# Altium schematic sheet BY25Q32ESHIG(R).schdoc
size 127 x 101 mm
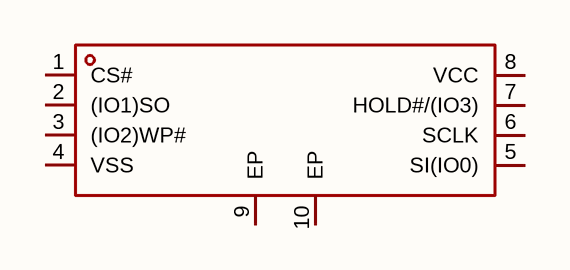
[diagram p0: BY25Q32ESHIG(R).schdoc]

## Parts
U?  by25q32eshig(r)  [DFN-8_L4.0-W3.0-P0.80-TL-EP_GT5YL24A1Y520]  (value not drawn)

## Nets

Not connected (* = marked no-connect by the designer): U? 1(CS#) 2((IO1)SO) 3((IO2)WP#) 4(VSS) 5(SI(IO0)) 6(SCLK) 7(HOLD#/(IO3)) 8(VCC) 9(EP) 10(EP)

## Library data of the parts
U? = by25q32eshig(r): 接口类型:SPI;存储容量:32Mbit;时钟频率(fc):120MHz;; Manufacturer: BOYAMICRO(博雅); AddInBom: yes; ModelId: ff23eaa3f9d946d4b17f951d9dd449de; ModelTransform: 118.18874,157.48,0,0,0,0,0,0,0; Interface: SPI; Memory Size: 32Mbit; Clock Frequency: 120MHz; Voltage - Supply: 2.7V~3.6V; Standby Supply Current: 2uA; Program / Erase Cycles: 100000次; Page Programming Time (Tpp): 450us; Block Erase Time(tBE): 180ms@(64KB); Data Retention - TDR (Year): 20年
